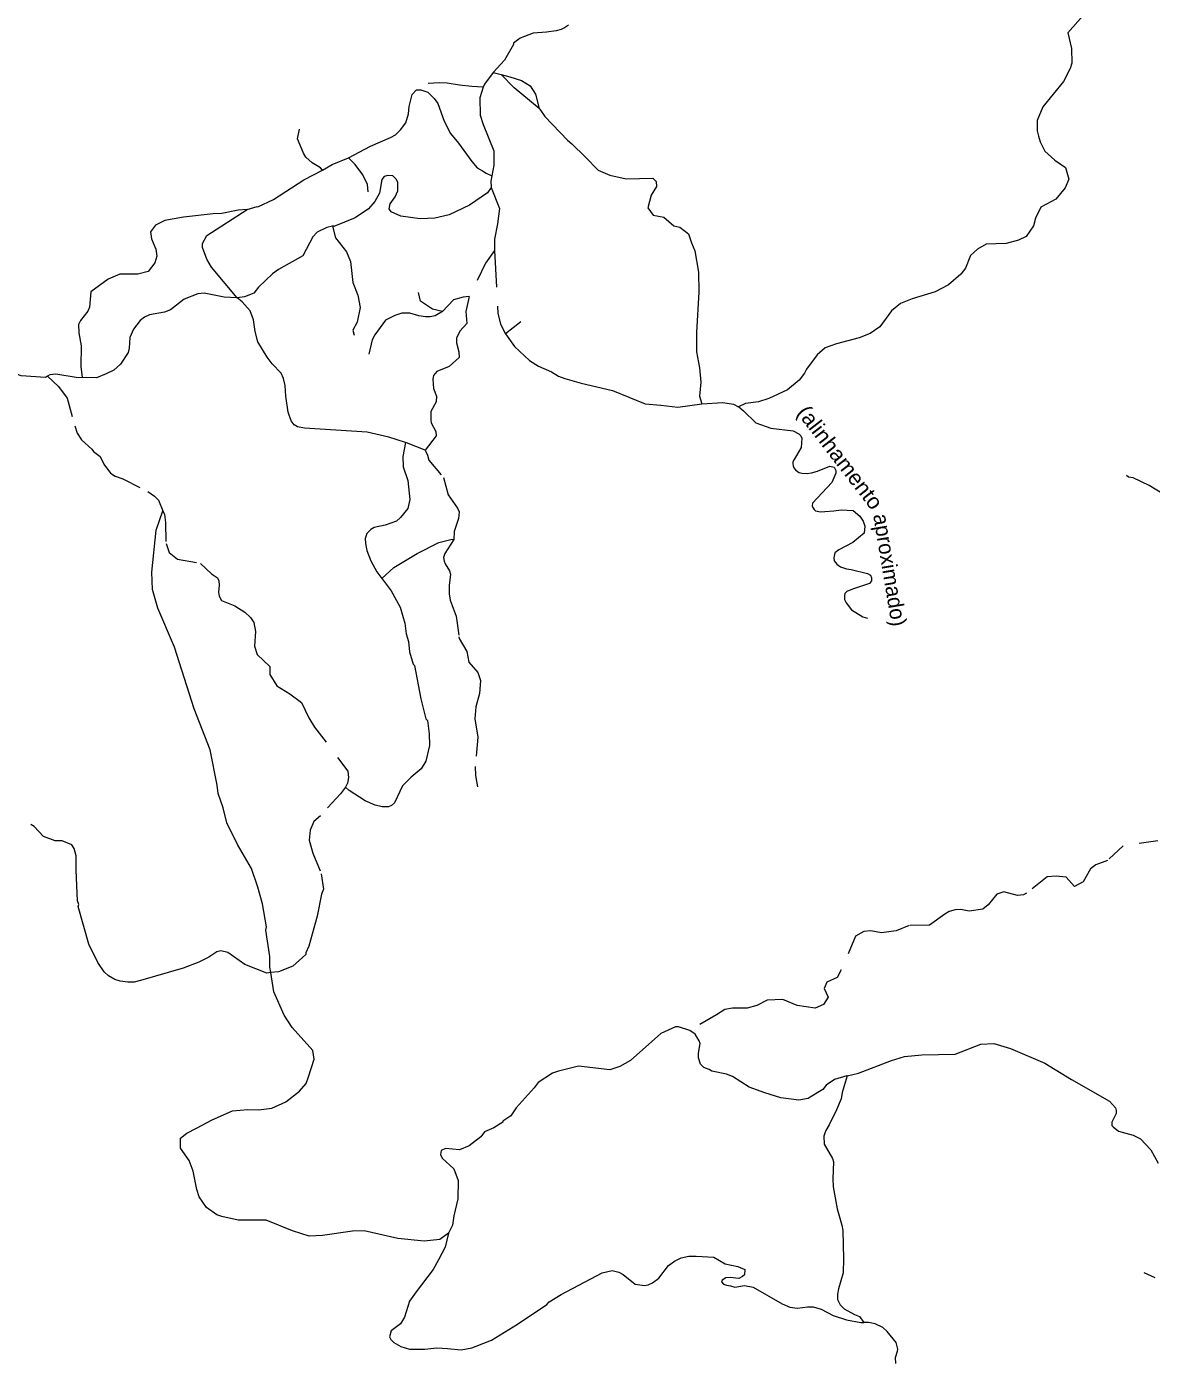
# Model space of a CAD drawing. Extents: x 423 to 448.8, y 7456.3 to 7484.
# Drawn here: x 428.88 to 434.76, y 7467.66 to 7474.65 of the extents above; entities that cross this region are included whole.
import ezdxf
from ezdxf.enums import TextEntityAlignment as Align

# ---------------------------------------------------------------- set-up
doc = ezdxf.new("R2010")
doc.units = 0
doc.header["$LTSCALE"] = 0.032
doc.linetypes.add('LONG_DASHED', pattern=[7.5, 6, -1.5])
doc.linetypes.add('MEDIUM_DASHED', pattern=[4.5, 3, -1.5])
for name, color, linetype, lineweight in [('5', 7, 'LONG_DASHED', 13), ('6', 7, 'MEDIUM_DASHED', 13), ('7', 7, 'Continuous', 13)]:
    doc.layers.add(name, color=color, linetype=linetype, lineweight=lineweight)
doc.layers.add('61', color=7, linetype='Continuous')

msp = doc.modelspace()

# ---------------------------------------------------------------- linework, layer by layer
at = {"layer": '5'}
for points in [[(431.7147, 7474.6587), (431.6937, 7474.644), (431.676, 7474.6354), (431.6506, 7474.6285), (431.6001, 7474.6221), (431.5295, 7474.6154), (431.4625, 7474.5896), (431.4281, 7474.563), (431.4281, 7474.5561), (431.3809, 7474.4754), (431.3216, 7474.411), (431.2761, 7474.35), (431.2693, 7474.3343), (431.252, 7474.2779), (431.2538, 7474.1868), (431.2684, 7474.1388), (431.3242, 7474.0013), (431.3247, 7473.9254), (431.3144, 7473.8702), (431.3093, 7473.8432), (431.3108, 7473.8088), (431.3534, 7473.699), (431.3444, 7473.6198), (431.3274, 7473.5396), (431.3286, 7473.481), (431.3452, 7473.1531), (431.3585, 7473.0944), (431.3855, 7473.0448), (431.4324, 7472.9776), (431.5109, 7472.9047), (431.558, 7472.8762), (431.6263, 7472.8453), (431.6629, 7472.8226), (431.695, 7472.8103), (431.7803, 7472.786), (431.9452, 7472.7482), (432.1152, 7472.6795), (432.1977, 7472.6718), (432.2861, 7472.6609), (432.4127, 7472.6784), (432.5223, 7472.6856), (432.5773, 7472.6761), (432.6034, 7472.6631), (432.6048, 7472.6624), (432.6305, 7472.6426), (432.6949, 7472.5791), (432.7731, 7472.5516), (432.8899, 7472.5379), (432.9191, 7472.5224), (432.9302, 7472.5121), (432.9354, 7472.4992), (432.9319, 7472.4501), (432.895, 7472.3876), (432.8884, 7472.3754), (432.8869, 7472.3652), (432.8899, 7472.3541), (432.8925, 7472.3448), (432.901, 7472.3343), (432.9115, 7472.3249), (432.9211, 7472.3201), (432.9343, 7472.3171), (432.9626, 7472.3147), (432.9854, 7472.3183), (433.017, 7472.3274), (433.0805, 7472.3532), (433.1029, 7472.3472), (433.1132, 7472.33), (433.1132, 7472.3163), (433.0917, 7472.2673), (432.9904, 7472.1591), (432.9886, 7472.1462), (432.992, 7472.1377), (432.9995, 7472.1265), (433.0055, 7472.1201), (433.0153, 7472.117), (433.0319, 7472.1148), (433.0546, 7472.1162), (433.1028, 7472.12), (433.1407, 7472.1247), (433.2025, 7472.1204), (433.2385, 7472.0921), (433.2548, 7472.0655), (433.2634, 7472.0397), (433.2609, 7472.0028), (433.2008, 7471.9539), (433.1286, 7471.9161), (433.108, 7471.8997), (433.1012, 7471.8731), (433.1041, 7471.8582), (433.117, 7471.8407), (433.137, 7471.827), (433.1678, 7471.8164), (433.1923, 7471.813), (433.2781, 7471.7924), (433.2934, 7471.7826), (433.2987, 7471.7701), (433.299, 7471.7544)], [(433.299, 7471.7544), (433.2883, 7471.739), (433.1991, 7471.7099), (433.1706, 7471.6979), (433.1597, 7471.6873), (433.1571, 7471.6753), (433.1584, 7471.6561), (433.1666, 7471.6391), (433.194, 7471.6026), (433.2542, 7471.5653), (433.2779, 7471.5583)]]:
    msp.add_lwpolyline(points, dxfattribs=at)
at = {"layer": '6'}
for points in [[(431.3286, 7473.481), (431.281, 7473.4136), (431.1961, 7473.239)], [(431.0563, 7473.1607), (431.0038, 7473.173), (430.9415, 7473.2158), (430.9305, 7473.2598)], [(431.1961, 7473.239), (431.1784, 7473.162), (431.1825, 7473.0978), (431.1473, 7473.0591), (431.1292, 7473.0223), (431.1301, 7472.9982), (431.142, 7472.9505), (431.1426, 7472.921), (431.0902, 7472.8747), (431.0257, 7472.8472), (431.0086, 7472.8271), (431.0049, 7472.8076), (431.0086, 7472.7583), (431.0244, 7472.7181), (431.0227, 7472.6889), (430.9953, 7472.6383), (430.9944, 7472.5928), (430.997, 7472.5791), (431.0219, 7472.5344), (431.0227, 7472.5121), (430.9651, 7472.4366), (430.9785, 7472.4099), (430.9841, 7472.3841), (431.0614, 7472.294), (431.0863, 7472.2037), (431.1344, 7472.1342), (431.143, 7472.1144), (431.1395, 7472.0792), (431.117, 7472.0121), (431.1146, 7471.9697), (431.0683, 7471.896), (431.0617, 7471.8747), (431.0653, 7471.8571), (431.0699, 7471.8426), (431.0931, 7471.8053), (431.0977, 7471.7887), (431.0906, 7471.7288), (431.0906, 7471.6859), (431.0958, 7471.6533), (431.1275, 7471.5691), (431.1421, 7471.4609), (431.143, 7471.4514), (431.1834, 7471.3844), (431.1937, 7471.3286), (431.2409, 7471.2736), (431.2555, 7471.2324), (431.2495, 7471.1645), (431.2297, 7471.095), (431.2254, 7471.0315), (431.24, 7470.937), (431.2271, 7470.7824), (431.2289, 7470.7368), (431.2392, 7470.6767)], [(431.1961, 7473.239), (431.1644, 7473.2365), (431.1131, 7473.2231), (431.0563, 7473.1607)], [(431.0563, 7473.1607), (431.0184, 7473.1385), (430.9919, 7473.1338), (430.9671, 7473.1338), (430.9317, 7473.1382), (430.8845, 7473.1528), (430.8441, 7473.1528), (430.8063, 7473.1407), (430.7573, 7473.1167), (430.7015, 7473.0394), (430.6886, 7473.0128), (430.6706, 7472.9389)], [(428.9916, 7472.8231), (429.0491, 7472.7695), (429.0931, 7472.7089), (429.1333, 7472.5645), (429.147, 7472.5258), (429.1693, 7472.4906), (429.2234, 7472.4425), (429.232, 7472.4288), (429.2664, 7472.403), (429.2861, 7472.3626), (429.3205, 7472.3171), (429.3454, 7472.2999), (429.3841, 7472.2862), (429.5164, 7472.2209), (429.5507, 7472.1969), (429.5713, 7472.1754), (429.5936, 7472.1194), (429.6031, 7472.0999), (429.6082, 7472.0586), (429.6108, 7471.9487), (429.628, 7471.9014), (429.6709, 7471.8671), (429.7912, 7471.8448), (429.8487, 7471.7898), (429.8805, 7471.7692), (429.8873, 7471.7537), (429.8882, 7471.7314), (429.8848, 7471.6945), (429.8882, 7471.673), (429.9002, 7471.6506), (429.9698, 7471.6223), (430.0221, 7471.5892), (430.0519, 7471.5622), (430.0703, 7471.5364), (430.078, 7471.4892), (430.0728, 7471.4128), (430.0875, 7471.3681), (430.1536, 7471.3063), (430.1536, 7471.2642), (430.1897, 7471.204), (430.2584, 7471.1629), (430.3193, 7471.1173), (430.3572, 7471.0383), (430.3872, 7470.9893), (430.5615, 7470.7592), (430.565, 7470.7257), (430.5589, 7470.6965), (430.5495, 7470.6759), (430.5487, 7470.6749), (430.5221, 7470.6408), (430.4191, 7470.5256), (430.3842, 7470.4957), (430.3649, 7470.45), (430.3597, 7470.3985), (430.3786, 7470.3306), (430.4224, 7470.2222)], [(434.7966, 7470.3951), (434.6151, 7470.368), (434.5329, 7470.2915), (434.4721, 7470.269), (434.444, 7470.2476), (434.4057, 7470.18), (434.3607, 7470.1564), (434.3168, 7470.2048), (434.2639, 7470.2104), (434.2167, 7470.2071), (434.1098, 7470.1204), (434.0941, 7470.1128), (434.0625, 7470.1091), (433.9905, 7470.1283), (433.9533, 7470.1159), (433.9094, 7470.0607), (433.8813, 7470.0371), (433.8093, 7470.0269), (433.7651, 7470.036), (433.7366, 7470.0348), (433.7054, 7470.0255), (433.6826, 7470.0112), (433.6016, 7469.9538), (433.4958, 7469.9515), (433.4271, 7469.9245), (433.3517, 7469.9132), (433.2953, 7469.9246), (433.2582, 7469.9201), (433.2154, 7469.8965), (433.1411, 7469.7209), (433.1186, 7469.6804), (433.0646, 7469.6556), (433.0522, 7469.6219), (433.0725, 7469.578), (433.0488, 7469.5397), (433.0049, 7469.5206), (432.9104, 7469.5341), (432.8361, 7469.5645), (432.7539, 7469.5622), (432.6998, 7469.5342), (432.6492, 7469.5207), (432.5726, 7469.5195), (432.5321, 7469.5128), (432.4882, 7469.4846), (432.3488, 7469.4039)], [(434.7811, 7468.1105), (434.7235, 7468.1372)]]:
    msp.add_lwpolyline(points, dxfattribs=at)
at = {"layer": '7'}
for p, q in [((431.3216, 7474.411), (431.3628, 7474.3996)), ((431.4649, 7473.1075), (431.3855, 7473.0448))]:
    msp.add_line(p, q, dxfattribs=at)
for points in [[(434.4031, 7474.7073), (434.325, 7474.6171), (434.3443, 7474.5364), (434.3464, 7474.46), (434.337, 7474.4308), (434.3027, 7474.3629), (434.1953, 7474.2306), (434.1644, 7474.1593), (434.1653, 7474.1061), (434.1721, 7474.0777), (434.1815, 7474.0477), (434.2056, 7473.9996), (434.2569, 7473.9515), (434.3126, 7473.9136), (434.331, 7473.8533), (434.3121, 7473.8084), (434.2618, 7473.7481), (434.1837, 7473.7068), (434.1568, 7473.65), (434.1454, 7473.6087), (434.1075, 7473.5538), (434.0672, 7473.5344), (434.0035, 7473.5165), (433.8985, 7473.5131), (433.8527, 7473.4871), (433.8169, 7473.4542), (433.7905, 7473.388), (433.7666, 7473.3571), (433.7015, 7473.3014), (433.6319, 7473.2644), (433.5108, 7473.2275), (433.4507, 7473.2026), (433.4043, 7473.1648), (433.3425, 7473.0806), (433.2918, 7473.0463), (433.2351, 7473.0231), (433.1157, 7472.9931), (433.0573, 7472.9715), (433.0144, 7472.9355), (432.9586, 7472.8591), (432.9491, 7472.8385), (432.9199, 7472.8032), (432.8598, 7472.7517), (432.7619, 7472.7062), (432.7086, 7472.6898), (432.6408, 7472.6796), (432.6034, 7472.6631)], [(431.561, 7474.2226), (431.4309, 7474.3311), (431.3628, 7474.3996)], [(431.3628, 7474.3996), (431.4078, 7474.3871), (431.4688, 7474.3688), (431.5138, 7474.3409), (431.5422, 7474.2977), (431.561, 7474.2226)], [(430.5639, 7473.9639), (430.6799, 7474.0256), (430.784, 7474.07), (430.8097, 7474.0855), (430.8372, 7474.1112), (430.8638, 7474.1482), (430.8776, 7474.1937), (430.8819, 7474.2323), (430.8974, 7474.2959), (430.9205, 7474.3191), (430.942, 7474.3199), (430.9789, 7474.3071), (431.0133, 7474.2753), (431.0313, 7474.2478), (431.0648, 7474.1559), (431.0983, 7474.0915), (431.1404, 7474.0417), (431.2086, 7473.9447), (431.238, 7473.9126), (431.2658, 7473.8974), (431.284, 7473.8847), (431.3144, 7473.8702)], [(431.2693, 7474.3343), (431.2103, 7474.3365), (431.1451, 7474.3435), (431.0807, 7474.3543), (431.0412, 7474.3557), (430.9819, 7474.3533)], [(431.561, 7474.2226), (431.5652, 7474.2191), (431.5911, 7474.1797), (431.7098, 7474.0563), (431.733, 7474.0378), (431.8013, 7473.9695), (431.8694, 7473.9006), (431.9316, 7473.8739), (432.0167, 7473.8544), (432.1561, 7473.8584), (432.1736, 7473.8405), (432.1745, 7473.814), (432.1477, 7473.7702), (432.1289, 7473.7027), (432.1571, 7473.6649), (432.2138, 7473.6542), (432.2652, 7473.6095), (432.297, 7473.6026), (432.3423, 7473.5681), (432.3579, 7473.5208), (432.3756, 7473.4786), (432.394, 7473.3677), (432.3955, 7473.2622), (432.3835, 7473.0532), (432.384, 7472.9507), (432.4004, 7472.8672), (432.4058, 7472.792), (432.3999, 7472.7187), (432.4127, 7472.6784)], [(430.4284, 7473.9), (430.4181, 7473.9129), (430.3752, 7473.9377), (430.3417, 7473.9678), (430.3293, 7473.9896), (430.2979, 7474.0642), (430.3079, 7474.115)], [(430.4284, 7473.9), (430.4799, 7473.9296), (430.5639, 7473.9639)], [(430.6677, 7473.7872), (430.6635, 7473.8256), (430.6403, 7473.8754), (430.5989, 7473.929), (430.5639, 7473.9639)], [(430.0347, 7473.694), (430.0875, 7473.7109), (430.09, 7473.7076), (430.1733, 7473.7471), (430.3305, 7473.8502), (430.4284, 7473.9)], [(431.3108, 7473.8088), (431.2912, 7473.7809), (431.1978, 7473.7169), (431.0913, 7473.6666), (431.0152, 7473.6484), (430.9401, 7473.6462), (430.8391, 7473.6599), (430.7883, 7473.6829), (430.7774, 7473.6988), (430.7829, 7473.7233), (430.8088, 7473.7602), (430.8218, 7473.7918), (430.8218, 7473.8364), (430.8157, 7473.851), (430.7968, 7473.8699), (430.7703, 7473.8725), (430.7505, 7473.8673), (430.7384, 7473.851), (430.7273, 7473.7806), (430.7032, 7473.7368), (430.6698, 7473.6981), (430.6002, 7473.6509), (430.4885, 7473.6062), (430.4834, 7473.6105), (430.4808, 7473.608)], [(430.0347, 7473.694), (429.9874, 7473.6911), (429.903, 7473.6741), (429.8565, 7473.6724), (429.7025, 7473.655), (429.6048, 7473.6371), (429.5553, 7473.6123), (429.5299, 7473.5782), (429.5349, 7473.541), (429.5571, 7473.4877), (429.5627, 7473.4499), (429.5528, 7473.4164), (429.517, 7473.3706), (429.4625, 7473.3557), (429.3691, 7473.356), (429.3085, 7473.33), (429.2181, 7473.2645), (429.21, 7473.1831), (429.2021, 7473.1625), (429.1631, 7473.1145), (429.1531, 7473.0939), (429.1557, 7473.0496), (429.167, 7472.9813), (429.1652, 7472.8745), (429.1728, 7472.8161)], [(429.9821, 7473.2326), (429.8487, 7473.3924), (429.8238, 7473.4345), (429.8015, 7473.4963), (429.8006, 7473.5161), (429.8247, 7473.559), (430.0347, 7473.694)], [(430.4808, 7473.608), (430.4508, 7473.6012), (430.4008, 7473.5757), (430.3778, 7473.5524), (430.3254, 7473.4525), (430.1991, 7473.3804), (430.1682, 7473.358), (430.0943, 7473.2885), (430.0695, 7473.2567), (430.0214, 7473.2378), (429.9821, 7473.2326)], [(430.4808, 7473.608), (430.4971, 7473.547), (430.5538, 7473.4731), (430.5744, 7473.4225), (430.5865, 7473.3134), (430.6139, 7473.2473), (430.6251, 7473.182), (430.6096, 7473.1064), (430.5882, 7473.0643), (430.595, 7473.0377)], [(429.9821, 7473.2326), (429.9154, 7473.2366), (429.8101, 7473.2576), (429.7774, 7473.2541), (429.7061, 7473.2266), (429.6348, 7473.1708), (429.6031, 7473.1571), (429.524, 7473.1442), (429.4983, 7473.1313), (429.4751, 7473.115), (429.4401, 7473.0698), (429.4222, 7473.025), (429.4175, 7472.9704), (429.4128, 7472.9473), (429.3723, 7472.8856), (429.3374, 7472.8555), (429.2984, 7472.8347), (429.247, 7472.8154), (429.1728, 7472.8161)], [(430.8628, 7472.4768), (430.775, 7472.5038), (430.6629, 7472.5301), (430.334, 7472.5507), (430.2979, 7472.5584), (430.2807, 7472.5696), (430.2652, 7472.5902), (430.2489, 7472.6358), (430.2369, 7472.7182), (430.2343, 7472.774), (430.2249, 7472.811), (430.212, 7472.8385), (430.1648, 7472.8874), (430.139, 7472.9226), (430.0909, 7473.0025), (430.0763, 7473.0574), (430.0686, 7473.1184), (430.0514, 7473.1656), (430.0091, 7473.2111), (429.9821, 7473.2326)], [(429.1728, 7472.8161), (429.1513, 7472.8144), (429.0354, 7472.8341), (429.0028, 7472.8298), (428.9916, 7472.8231), (428.9813, 7472.817), (428.8541, 7472.8247), (428.8155, 7472.8393), (428.7863, 7472.8565), (428.7253, 7472.9303), (428.685, 7472.9578), (428.6246, 7472.9723), (428.604, 7472.9678)], [(430.8628, 7472.4768), (430.8492, 7472.4035), (430.8506, 7472.349), (430.8741, 7472.2776), (430.8862, 7472.1784), (430.875, 7472.1316), (430.8372, 7472.0844), (430.8149, 7472.0646), (430.7556, 7472.044), (430.6981, 7472.032), (430.6809, 7472.0225), (430.6607, 7472.0011), (430.6514, 7471.9741), (430.6534, 7471.9495), (430.6603, 7471.9117), (430.6818, 7471.8577), (430.7127, 7471.801), (430.7381, 7471.7661)], [(430.9651, 7472.4366), (430.8679, 7472.4752), (430.8628, 7472.4768)], [(436.385, 7471.9059), (436.0625, 7471.953), (436.0229, 7471.9633), (435.9729, 7471.9884), (435.8262, 7472.0354), (435.7859, 7472.032), (435.7558, 7472.0226), (435.6429, 7471.9468), (435.5832, 7471.9339), (435.5479, 7471.9424), (435.5071, 7471.9325), (435.4662, 7471.9534), (435.4304, 7471.9793), (435.3866, 7472.0202), (435.3154, 7472.0407), (435.2229, 7472.0387), (435.086, 7472.0662), (435.0164, 7472.1031), (434.9333, 7472.1396), (434.7506, 7472.251), (434.6665, 7472.2914), (434.6416, 7472.2954), (434.6324, 7472.3034)], [(430.1586, 7469.7059), (430.154, 7469.7343), (430.154, 7469.7893), (430.1325, 7469.9276), (430.1364, 7469.945), (430.1156, 7470.0647), (430.09, 7470.152), (430.0574, 7470.2507), (429.9836, 7470.3747), (429.9294, 7470.4889), (429.909, 7470.5662), (429.8826, 7470.6415), (429.8786, 7470.6864), (429.8408, 7470.871), (429.7582, 7471.0845), (429.6553, 7471.4063), (429.5687, 7471.6109), (429.5393, 7471.7082), (429.5358, 7471.7995), (429.5586, 7472.0181), (429.5936, 7472.1194)], [(430.7381, 7471.7661), (430.8016, 7471.8226), (430.9245, 7471.8968), (431.0364, 7471.9541), (431.106, 7471.9709), (431.1146, 7471.9697)], [(430.7381, 7471.7661), (430.7401, 7471.7634), (430.7883, 7471.7013), (430.8355, 7471.6154), (430.8594, 7471.5328), (430.8668, 7471.4757), (430.8782, 7471.4372), (430.8839, 7471.3827), (430.9033, 7471.3187), (430.9094, 7471.3105), (430.9437, 7471.1362), (430.9695, 7471.0323), (430.9772, 7471.0237), (430.9858, 7470.9542), (430.9875, 7470.8923), (430.9695, 7470.8116), (430.9446, 7470.7712), (430.893, 7470.7282), (430.8475, 7470.6819), (430.8046, 7470.5934), (430.7891, 7470.5788), (430.7737, 7470.5719), (430.7411, 7470.5728), (430.7041, 7470.5814), (430.6517, 7470.6029), (430.5675, 7470.657), (430.5487, 7470.6749)], [(430.1586, 7469.7059), (430.1374, 7469.7035), (430.0224, 7469.748), (429.9346, 7469.8102), (429.8968, 7469.8188), (429.8762, 7469.8144), (429.8349, 7469.787), (429.7826, 7469.7603), (429.701, 7469.7294), (429.4777, 7469.6642), (429.4442, 7469.6564), (429.4107, 7469.6556), (429.3704, 7469.6607), (429.3437, 7469.6693), (429.3102, 7469.6891), (429.287, 7469.7097), (429.2544, 7469.7587), (429.208, 7469.8539), (429.1519, 7470.0514), (429.1548, 7470.061), (429.1479, 7470.0807), (429.1402, 7470.2404), (429.141, 7470.3169), (429.1298, 7470.3547), (429.1187, 7470.3744), (429.068, 7470.3942), (429.0311, 7470.3942), (428.971, 7470.4173), (428.922, 7470.4689), (428.904, 7470.4803)], [(430.4224, 7470.2222), (430.4347, 7470.1428), (430.4236, 7470.116), (430.4006, 7470), (430.358, 7469.8436), (430.3417, 7469.8084), (430.3425, 7469.7999), (430.2743, 7469.7388), (430.1991, 7469.7105), (430.1586, 7469.7059)], [(431.0872, 7468.3437), (431.042, 7468.3115), (430.9608, 7468.3021), (430.8231, 7468.3153), (430.6466, 7468.3559), (430.5863, 7468.354), (430.4287, 7468.3322), (430.3589, 7468.3284), (430.2721, 7468.3568), (430.1334, 7468.4125), (429.9881, 7468.4125), (429.9032, 7468.4314), (429.8771, 7468.44), (429.8232, 7468.4784), (429.7848, 7468.5343), (429.772, 7468.5722), (429.7522, 7468.6676), (429.7314, 7468.7243), (429.6865, 7468.788), (429.6868, 7468.8399), (429.7189, 7468.8665), (429.7695, 7468.8932), (429.8512, 7468.9358), (429.9588, 7468.9842), (430.039, 7468.9904), (430.0937, 7468.9885), (430.1635, 7468.9979), (430.2371, 7469.03), (430.3088, 7469.0866), (430.3428, 7469.1263), (430.356, 7469.1602), (430.3849, 7469.2542), (430.379, 7469.2985), (430.2706, 7469.4193), (430.2283, 7469.4832), (430.1747, 7469.6048), (430.162, 7469.6844), (430.1586, 7469.7059)], [(433.172, 7469.1668), (433.1705, 7469.1665), (433.1049, 7469.1465), (433.0617, 7469.1176), (433.0452, 7469.0952), (432.979, 7469.0545), (432.9679, 7469.0472), (432.9187, 7469.0383), (432.8254, 7469.0505), (432.7411, 7469.0769), (432.659, 7469.1078), (432.572, 7469.1625), (432.5407, 7469.1754), (432.4636, 7469.1904), (432.4497, 7469.1999), (432.4223, 7469.2107), (432.4049, 7469.2277), (432.3952, 7469.2597), (432.3943, 7469.284), (432.4034, 7469.3354), (432.3975, 7469.3498), (432.3763, 7469.3833), (432.3488, 7469.4039), (432.2904, 7469.4219), (432.2749, 7469.4219), (432.1977, 7469.3876), (432.0387, 7469.2459), (431.9831, 7469.2144), (431.9304, 7469.1985), (431.7676, 7469.217), (431.6631, 7469.1901), (431.6308, 7469.18), (431.5562, 7469.1315), (431.5352, 7469.1039), (431.4411, 7468.9987), (431.4127, 7468.9564), (431.3719, 7468.9294), (431.3709, 7468.9245), (431.3241, 7468.8945), (431.2758, 7468.8731), (431.2569, 7468.8472), (431.195, 7468.7999), (431.145, 7468.7789), (431.0713, 7468.7859), (431.0485, 7468.7764), (431.0453, 7468.7558), (431.0543, 7468.7363), (431.1156, 7468.6798), (431.1375, 7468.6199), (431.136, 7468.5237), (431.1146, 7468.4345), (431.1091, 7468.3865), (431.0872, 7468.3437)], [(433.172, 7469.1668), (433.2309, 7469.1807), (433.4027, 7469.2459), (433.471, 7469.2673), (433.5628, 7469.2759), (433.7368, 7469.2791), (433.8711, 7469.3319), (433.9384, 7469.3349), (434.0248, 7469.3084), (434.2053, 7469.2331), (434.344, 7469.1476), (434.5431, 7469.0346), (434.5749, 7468.9985), (434.5783, 7468.9857), (434.5784, 7468.9693), (434.5552, 7468.9238), (434.556, 7468.9075), (434.562, 7468.8998), (434.5904, 7468.8766), (434.666, 7468.856), (434.7055, 7468.8362), (434.7595, 7468.7787), (434.7973, 7468.71)], [(433.172, 7469.1668), (433.1458, 7469.0785), (433.1396, 7469.0453), (433.1162, 7468.9892), (433.0781, 7468.9104), (433.0605, 7468.8801), (433.0547, 7468.867), (433.049, 7468.8506), (433.0518, 7468.8083), (433.0945, 7468.7349), (433.1002, 7468.7173), (433.0969, 7468.6271), (433.0984, 7468.5865), (433.1197, 7468.4705), (433.1439, 7468.3852), (433.1488, 7468.3573), (433.1533, 7468.2093), (433.1503, 7468.1361), (433.1268, 7468.0526), (433.1209, 7468.0251), (433.1214, 7467.9971), (433.1356, 7467.9697), (433.1557, 7467.949), (433.2107, 7467.9196), (433.2353, 7467.9078), (433.2591, 7467.8767)], [(431.0872, 7468.3437), (431.0693, 7468.271), (431.0353, 7468.2048), (431.007, 7468.1536), (430.9193, 7468.0375), (430.8839, 7467.9893), (430.8579, 7467.9055), (430.8359, 7467.8696), (430.7883, 7467.8342), (430.7794, 7467.8025), (430.7863, 7467.7886), (430.8022, 7467.7722), (430.8384, 7467.7514), (430.8834, 7467.737), (430.9644, 7467.7375), (431.0267, 7467.7446), (431.0815, 7467.7408), (431.1539, 7467.7341), (431.2088, 7467.7446), (431.2315, 7467.7531), (431.3127, 7467.7853), (431.4487, 7467.8688), (431.6013, 7467.9706), (431.6137, 7467.9848), (431.6759, 7468.0226), (431.8902, 7468.1363), (431.9434, 7468.1492), (431.9778, 7468.1406), (432.0009, 7468.1286), (432.0628, 7468.077), (432.1126, 7468.0702), (432.1307, 7468.0736), (432.1547, 7468.0848), (432.1865, 7468.1088), (432.2372, 7468.1741), (432.2689, 7468.1981), (432.3033, 7468.2145), (432.3437, 7468.223), (432.3815, 7468.2239), (432.4747, 7468.218), (432.5344, 7468.1831), (432.5996, 7468.1699), (432.6374, 7468.1536), (432.6355, 7468.1257), (432.6241, 7468.1177), (432.6045, 7468.1073), (432.5607, 7468.1122), (432.5369, 7468.1107), (432.518, 7468.0978), (432.514, 7468.0888), (432.525, 7468.0774), (432.5408, 7468.0725), (432.5613, 7468.0683), (432.5846, 7468.0621), (432.6349, 7468.0703), (432.68, 7468.0621), (432.8325, 7467.975), (432.8713, 7467.9571), (432.9113, 7467.9527), (432.9644, 7467.9582), (432.9947, 7467.9582), (433.036, 7467.9465), (433.0989, 7467.9129), (433.1689, 7467.8908), (433.2435, 7467.8769), (433.2591, 7467.8767)], [(433.4267, 7467.6631), (433.4241, 7467.6948), (433.4344, 7467.7266), (433.4361, 7467.7369), (433.4275, 7467.7721), (433.3802, 7467.8305), (433.3579, 7467.8511), (433.3176, 7467.8692), (433.2836, 7467.8765), (433.2591, 7467.8767)]]:
    msp.add_lwpolyline(points, dxfattribs=at)

# ---------------------------------------------------------------- texts
at = {"layer": '61', "width": 1.05}
msp.add_text('(alinhamento', height=0.08, rotation=307.646, dxfattribs=at).set_placement((433.1033, 7472.3746), align=Align.CENTER)
at = {"layer": '61'}
msp.add_text(' aproximado)', height=0.08, rotation=279.497, dxfattribs=at).set_placement((433.3537, 7471.8188), align=Align.CENTER)

doc.saveas('drawing.dxf')
